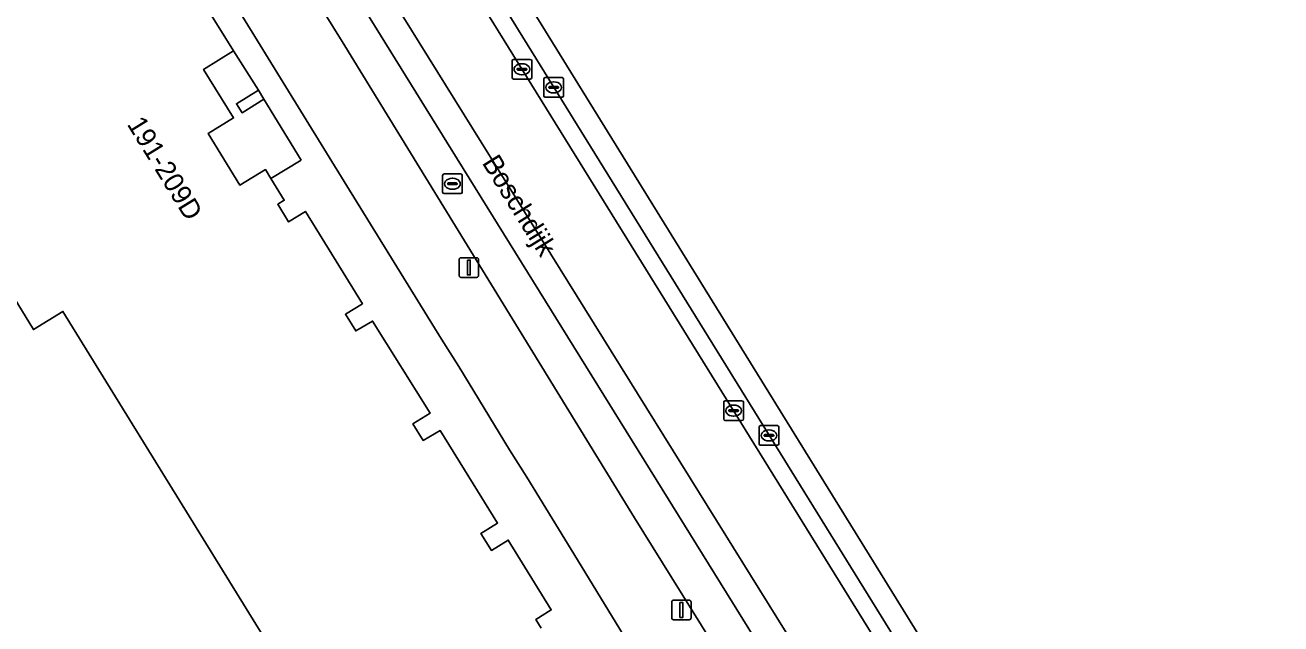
# Model space of a CAD drawing. Extents: x 159888 to 160761, y 384031 to 384750.
# Drawn here: x 160569.1 to 160633, y 384354.7 to 384385.2 of the extents above; entities that cross this region are included whole.
import ezdxf

# ---------------------------------------------------------------- set-up
doc = ezdxf.new("R2010")
doc.units = 0
for name, color, linetype in [('IMGEO_Berm_open', 7, 'Continuous'), ('IMGEO_Erf', 7, 'Continuous'), ('IMGEO_Kolk', 7, 'Continuous'), ('IMGEO_Lichtmast', 7, 'Continuous'), ('IMGEO_Muur', 7, 'Continuous'), ('IMGEO_Openbare_ruimte_label', 7, 'Continuous'), ('IMGEO_Pand', 7, 'Continuous'), ('IMGEO_Pand_nummerreeks', 7, 'Continuous'), ('IMGEO_Pand_overbouw', 7, 'Continuous'), ('IMGEO_Parkeervlak_gesloten', 7, 'Continuous'), ('IMGEO_Rijbaan_lokaal_gesloten', 7, 'Continuous'), ('IMGEO_Rioolput', 7, 'Continuous'), ('IMGEO_Voetpad_open', 7, 'Continuous')]:
    doc.layers.add(name, color=color, linetype=linetype)

msp = doc.modelspace()

# ---------------------------------------------------------------- linework, layer by layer
at = {"layer": 'IMGEO_Berm_open'}
msp.add_lwpolyline([(160573.734, 384418.106), (160547.482, 384460.166), (160546.333, 384462.102), (160545.604, 384461.675), (160546.003, 384460.9), (160546.729, 384459.74), (160564.541, 384431.158), (160615.861, 384348.269), (160631.369, 384323.299), (160632.074, 384323.722), (160631.044, 384325.378)], close=True, dxfattribs=at)
at = {"layer": 'IMGEO_Erf'}
for points in [[(160600.365, 384352.829), (160597.222, 384357.971), (160594.642, 384362.181), (160593.757, 384363.576), (160591.184, 384367.806), (160590.298, 384369.214), (160585.486, 384377.009), (160580.046, 384385.856), (160577.427, 384390.077), (160576.576, 384391.436), (160573.976, 384395.655), (160573.139, 384397.008), (160570.55, 384401.238), (160566.359, 384407.814)], [(160577.492, 384387.466), (160578.932, 384385.154), (160579.715, 384383.896), (160578.196, 384382.943), (160579.718, 384380.474), (160578.421, 384379.675), (160580.035, 384377.056), (160581.338, 384377.848), (160581.621, 384377.388), (160582.302, 384376.281), (160581.969, 384376.076), (160582.52, 384375.182), (160583.379, 384375.711), (160586.275, 384371.011), (160585.411, 384370.479), (160585.935, 384369.628), (160586.793, 384370.131), (160589.717, 384365.431), (160588.848, 384364.899), (160589.37, 384364.046), (160590.239, 384364.551), (160593.157, 384359.834), (160592.309, 384359.309), (160592.846, 384358.444), (160593.698, 384358.972), (160595.887, 384355.417), (160595.104, 384354.934), (160595.373, 384354.493)], [(160582.063, 384352.728), (160571.03, 384370.619), (160569.536, 384369.697), (160567.598, 384372.839)]]:
    msp.add_lwpolyline(points, dxfattribs=at)
msp.add_lwpolyline([(160579.867, 384381.201), (160580.982, 384381.888), (160581.265, 384381.428), (160580.15, 384380.741)], close=True, dxfattribs=at)
at = {"layer": 'IMGEO_Kolk'}
for p, q in [((160593.97, 384383.455), (160594.822, 384383.455)), ((160593.895, 384382.529), (160593.895, 384383.381)), ((160594.154, 384382.949), (160594.154, 384382.961)), ((160594.592, 384382.912), (160594.194, 384382.912)), ((160594.197, 384382.998), (160594.595, 384382.998)), ((160594.383, 384383.235), (160594.408, 384383.235)), ((160594.638, 384382.961), (160594.638, 384382.949)), ((160594.896, 384383.381), (160594.896, 384382.529)), ((160594.822, 384382.455), (160593.97, 384382.455)), ((160594.406, 384382.675), (160594.381, 384382.675)), ((160595.511, 384381.605), (160595.511, 384382.457)), ((160595.586, 384382.531), (160596.438, 384382.531)), ((160595.999, 384382.311), (160596.024, 384382.311)), ((160596.512, 384382.457), (160596.512, 384381.605)), ((160596.438, 384381.531), (160595.586, 384381.531)), ((160595.77, 384382.025), (160595.77, 384382.037)), ((160596.208, 384381.988), (160595.81, 384381.988)), ((160595.813, 384382.074), (160596.211, 384382.074)), ((160596.022, 384381.751), (160595.997, 384381.751)), ((160596.254, 384382.037), (160596.254, 384382.025)), ((160604.668, 384365.141), (160604.668, 384365.993)), ((160604.743, 384366.067), (160605.595, 384366.067)), ((160604.927, 384365.561), (160604.927, 384365.573)), ((160604.97, 384365.61), (160605.368, 384365.61)), ((160605.156, 384365.847), (160605.181, 384365.847)), ((160605.411, 384365.573), (160605.411, 384365.561)), ((160605.669, 384365.993), (160605.669, 384365.141)), ((160605.595, 384365.067), (160604.743, 384365.067)), ((160605.365, 384365.524), (160604.967, 384365.524)), ((160605.179, 384365.287), (160605.154, 384365.287)), ((160606.469, 384363.876), (160606.469, 384364.728)), ((160606.544, 384364.802), (160607.396, 384364.802)), ((160606.728, 384364.296), (160606.728, 384364.308)), ((160607.166, 384364.259), (160606.768, 384364.259)), ((160606.771, 384364.345), (160607.169, 384364.345)), ((160606.957, 384364.582), (160606.982, 384364.582)), ((160607.212, 384364.308), (160607.212, 384364.296)), ((160607.47, 384364.728), (160607.47, 384363.876)), ((160607.396, 384363.802), (160606.544, 384363.802)), ((160606.98, 384364.022), (160606.955, 384364.022))]:
    msp.add_line(p, q, dxfattribs=at)
for points in [[(160593.97, 384383.455), (160594.822, 384383.455)], [(160593.895, 384382.529), (160593.895, 384383.381)], [(160594.896, 384383.381), (160594.896, 384382.529)], [(160594.822, 384382.455), (160593.97, 384382.455)], [(160595.511, 384381.605), (160595.511, 384382.457)], [(160595.586, 384382.531), (160596.438, 384382.531)], [(160596.512, 384382.457), (160596.512, 384381.605)], [(160596.438, 384381.531), (160595.586, 384381.531)], [(160604.668, 384365.141), (160604.668, 384365.993)], [(160604.743, 384366.067), (160605.595, 384366.067)], [(160605.669, 384365.993), (160605.669, 384365.141)], [(160605.595, 384365.067), (160604.743, 384365.067)], [(160606.469, 384363.876), (160606.469, 384364.728)], [(160606.544, 384364.802), (160607.396, 384364.802)], [(160607.47, 384364.728), (160607.47, 384363.876)], [(160607.396, 384363.802), (160606.544, 384363.802)]]:
    msp.add_lwpolyline(points, dxfattribs=at)
for centre, radius, start, end in [((160593.972, 384383.379), 0.0765, 91.55205, 178.44795), ((160593.972, 384383.379), 0.0765, 91.55205, 178.44795), ((160594.82, 384383.379), 0.0765, 1.55205, 88.44795), ((160594.82, 384383.379), 0.0765, 1.55205, 88.44795), ((160594.194, 384382.958), 0.0403, 85.87752, 175.75265), ((160594.191, 384382.948), 0.0366, 178.93798, 274.71019), ((160594.595, 384382.955), 0.043, 264.86636, 352.45326), ((160594.599, 384382.96), 0.0386, 1.73085, 96.63898), ((160593.972, 384382.531), 0.0765, 181.55205, 268.44795), ((160593.972, 384382.531), 0.0765, 181.55205, 268.44795), ((160594.82, 384382.531), 0.0765, 271.55205, 358.44795), ((160594.82, 384382.531), 0.0765, 271.55205, 358.44795), ((160595.588, 384382.455), 0.0765, 91.55205, 178.44795), ((160595.588, 384382.455), 0.0765, 91.55205, 178.44795), ((160596.436, 384382.455), 0.0765, 1.55205, 88.44795), ((160596.436, 384382.455), 0.0765, 1.55205, 88.44795), ((160595.588, 384381.607), 0.0765, 181.55205, 268.44795), ((160595.588, 384381.607), 0.0765, 181.55205, 268.44795), ((160595.81, 384382.034), 0.0403, 85.87752, 175.75265), ((160595.807, 384382.024), 0.0366, 178.93798, 274.71019), ((160596.211, 384382.031), 0.043, 264.86636, 352.45326), ((160596.215, 384382.036), 0.0386, 1.73085, 96.63898), ((160596.436, 384381.607), 0.0765, 271.55205, 358.44795), ((160596.436, 384381.607), 0.0765, 271.55205, 358.44795), ((160604.745, 384365.991), 0.0765, 91.55205, 178.44795), ((160604.745, 384365.991), 0.0765, 91.55205, 178.44795), ((160604.967, 384365.57), 0.0403, 85.87752, 175.75265), ((160604.964, 384365.56), 0.0366, 178.93798, 274.71019), ((160605.368, 384365.567), 0.043, 264.86636, 352.45326), ((160605.372, 384365.572), 0.0386, 1.73085, 96.63898), ((160605.593, 384365.991), 0.0765, 1.55205, 88.44795), ((160605.593, 384365.991), 0.0765, 1.55205, 88.44795), ((160604.745, 384365.143), 0.0765, 181.55205, 268.44795), ((160604.745, 384365.143), 0.0765, 181.55205, 268.44795), ((160605.593, 384365.143), 0.0765, 271.55205, 358.44795), ((160605.593, 384365.143), 0.0765, 271.55205, 358.44795), ((160606.546, 384364.726), 0.0765, 91.55205, 178.44795), ((160606.546, 384364.726), 0.0765, 91.55205, 178.44795), ((160606.768, 384364.305), 0.0403, 85.87752, 175.75265), ((160606.765, 384364.295), 0.0366, 178.93798, 274.71019), ((160607.169, 384364.302), 0.043, 264.86636, 352.45326), ((160607.173, 384364.307), 0.0386, 1.73085, 96.63898), ((160607.394, 384364.726), 0.0765, 1.55205, 88.44795), ((160607.394, 384364.726), 0.0765, 1.55205, 88.44795), ((160606.546, 384363.878), 0.0765, 181.55205, 268.44795), ((160606.546, 384363.878), 0.0765, 181.55205, 268.44795), ((160607.394, 384363.878), 0.0765, 271.55205, 358.44795), ((160607.394, 384363.878), 0.0765, 271.55205, 358.44795)]:
    msp.add_arc(centre, radius, start, end, dxfattribs=at)
for centre, major_axis, ratio, start_param, end_param in [((160594.382, 384382.955), (-0.387, 0.002), 0.722429, 4.712389, 7.853982), ((160594.407, 384382.955), (-0.39, 0.002), 0.717154, 1.570796, 4.712389), ((160595.998, 384382.031), (-0.387, 0.002), 0.722429, 4.712389, 7.853982), ((160596.023, 384382.031), (-0.39, 0.002), 0.717154, 1.570796, 4.712389), ((160605.155, 384365.567), (-0.387, 0.002), 0.722429, 4.712389, 7.853982), ((160605.18, 384365.567), (-0.39, 0.002), 0.717154, 1.570796, 4.712389), ((160606.956, 384364.302), (-0.387, 0.002), 0.722429, 4.712389, 7.853982), ((160606.981, 384364.302), (-0.39, 0.002), 0.717154, 1.570796, 4.712389)]:
    msp.add_ellipse(centre, major_axis=major_axis, ratio=ratio, start_param=start_param, end_param=end_param, dxfattribs=at)
at = {"layer": 'IMGEO_Lichtmast'}
for p, q in [((160591.198, 384372.456), (160591.198, 384373.256)), ((160591.198, 384373.256), (160591.198, 384372.456)), ((160591.298, 384373.356), (160592.088, 384373.356)), ((160592.088, 384373.356), (160591.298, 384373.356)), ((160592.188, 384373.256), (160592.188, 384372.456)), ((160592.188, 384372.456), (160592.188, 384373.256)), ((160592.088, 384372.356), (160591.298, 384372.356)), ((160591.298, 384372.356), (160592.088, 384372.356)), ((160602.017, 384355.011), (160602.017, 384355.811)), ((160602.017, 384355.811), (160602.017, 384355.011)), ((160602.117, 384355.911), (160602.907, 384355.911)), ((160602.907, 384355.911), (160602.117, 384355.911)), ((160603.007, 384355.811), (160603.007, 384355.011)), ((160603.007, 384355.011), (160603.007, 384355.811)), ((160602.907, 384354.911), (160602.117, 384354.911)), ((160602.117, 384354.911), (160602.907, 384354.911))]:
    msp.add_line(p, q, dxfattribs=at)
for points in [[(160591.618, 384373.231), (160591.768, 384373.231), (160591.768, 384372.481), (160591.618, 384372.481), (160591.618, 384373.231)], [(160602.437, 384355.786), (160602.587, 384355.786), (160602.587, 384355.036), (160602.437, 384355.036), (160602.437, 384355.786)]]:
    msp.add_lwpolyline(points, dxfattribs=at)
for centre, start, end in [((160591.298, 384373.256), 90, 180), ((160591.298, 384373.256), 90, 180), ((160592.088, 384373.256), 0, 90), ((160592.088, 384373.256), 360, 90), ((160591.298, 384372.456), 180, 270), ((160591.298, 384372.456), 180, 270), ((160592.088, 384372.456), 270, 0), ((160592.088, 384372.456), 270, 0), ((160602.117, 384355.811), 90, 180), ((160602.117, 384355.811), 90, 180), ((160602.907, 384355.811), 0, 90), ((160602.907, 384355.811), 360, 90), ((160602.117, 384355.011), 180, 270), ((160602.117, 384355.011), 180, 270), ((160602.907, 384355.011), 270, 0), ((160602.907, 384355.011), 270, 0)]:
    msp.add_arc(centre, 0.1, start, end, dxfattribs=at)
at = {"layer": 'IMGEO_Muur'}
for points in [[(160585.486, 384377.009), (160590.298, 384369.214)], [(160591.184, 384367.806), (160593.757, 384363.576)], [(160594.642, 384362.181), (160597.222, 384357.971)]]:
    msp.add_lwpolyline(points, dxfattribs=at)
at = {"layer": 'IMGEO_Pand'}
for points in [[(160595.373, 384354.493), (160595.104, 384354.934), (160595.887, 384355.417), (160593.698, 384358.972), (160592.846, 384358.444), (160592.309, 384359.309), (160593.157, 384359.834), (160590.239, 384364.551), (160589.37, 384364.046), (160588.848, 384364.899), (160589.717, 384365.431), (160586.793, 384370.131), (160585.935, 384369.628), (160585.411, 384370.479), (160586.275, 384371.011), (160583.379, 384375.711), (160582.52, 384375.182), (160581.969, 384376.076), (160582.302, 384376.281), (160581.621, 384377.388), (160581.338, 384377.848), (160580.035, 384377.056), (160578.421, 384379.675), (160579.718, 384380.474), (160578.196, 384382.943), (160579.715, 384383.896), (160578.932, 384385.154), (160577.492, 384387.466)], [(160567.598, 384372.839), (160569.536, 384369.697), (160571.03, 384370.619), (160582.063, 384352.728)]]:
    msp.add_lwpolyline(points, dxfattribs=at)
msp.add_lwpolyline([(160581.265, 384381.428), (160580.982, 384381.888), (160579.867, 384381.201), (160580.15, 384380.741)], close=True, dxfattribs=at)
at = {"layer": 'IMGEO_Pand_overbouw'}
msp.add_lwpolyline([(160583.168, 384378.329), (160581.265, 384381.428), (160580.15, 384380.741), (160579.867, 384381.201), (160580.982, 384381.888), (160579.715, 384383.896), (160578.196, 384382.943), (160579.718, 384380.474), (160578.421, 384379.675), (160580.035, 384377.056), (160581.338, 384377.848), (160581.621, 384377.388)], close=True, dxfattribs=at)
at = {"layer": 'IMGEO_Parkeervlak_gesloten'}
for points in [[(160591.404, 384377.897), (160543.713, 384454.868), (160537.603, 384464.743), (160537.564, 384464.718)], [(160537.553, 384461.036), (160540.083, 384456.992), (160542.538, 384453.014), (160544.582, 384449.757), (160546.017, 384447.47), (160547.886, 384444.522), (160552.792, 384436.596), (160555.44, 384432.318), (160560.546, 384424.068), (160561.084, 384423.337), (160563.566, 384419.321), (160564.854, 384417.108), (160570.857, 384407.526), (160585.252, 384384.362), (160600.12, 384360.1), (160613.675, 384338.3), (160614.145, 384337.587), (160615.758, 384338.612), (160591.404, 384377.897)]]:
    msp.add_lwpolyline(points, dxfattribs=at)
at = {"layer": 'IMGEO_Rijbaan_lokaal_gesloten'}
for points in [[(160530.872, 384485.299), (160529.392, 384487.663), (160528.599, 384488.928), (160527.089, 384491.477), (160521.986, 384499.927), (160522.875, 384494.017), (160521.397, 384493.999), (160525.927, 384486.643), (160525.936, 384486.628), (160565.675, 384422.118), (160628.254, 384321.427), (160631.369, 384323.299), (160615.861, 384348.269), (160564.541, 384431.158), (160546.729, 384459.74), (160546.003, 384460.9), (160545.604, 384461.675)], [(160633.021, 384324.291), (160626.323, 384335.141), (160581.707, 384407.406), (160547.381, 384462.76), (160546.333, 384462.102), (160547.482, 384460.166), (160573.734, 384418.106), (160631.044, 384325.378), (160632.074, 384323.722), (160633.021, 384324.291)]]:
    msp.add_lwpolyline(points, dxfattribs=at)
msp.add_lwpolyline([(160525.936, 384486.628), (160525.927, 384486.643), (160521.397, 384493.999), (160519.494, 384493.976), (160523.701, 384487.143), (160524.133, 384486.422), (160537.603, 384464.743), (160543.713, 384454.868), (160591.404, 384377.897), (160615.758, 384338.612), (160624.721, 384324.154), (160626.898, 384320.642), (160628.254, 384321.427), (160565.675, 384422.118)], close=True, dxfattribs=at)
at = {"layer": 'IMGEO_Rioolput'}
for p, q in [((160590.358, 384376.694), (160590.358, 384377.546)), ((160590.433, 384377.62), (160591.285, 384377.62)), ((160590.617, 384377.114), (160590.617, 384377.126)), ((160591.055, 384377.077), (160590.657, 384377.077)), ((160590.66, 384377.163), (160591.058, 384377.163)), ((160590.846, 384377.4), (160590.871, 384377.4)), ((160591.101, 384377.126), (160591.101, 384377.114)), ((160591.359, 384377.546), (160591.359, 384376.694)), ((160591.285, 384376.62), (160590.433, 384376.62)), ((160590.869, 384376.84), (160590.844, 384376.84))]:
    msp.add_line(p, q, dxfattribs=at)
for points in [[(160590.358, 384376.694), (160590.358, 384377.546)], [(160590.433, 384377.62), (160591.285, 384377.62)], [(160591.359, 384377.546), (160591.359, 384376.694)], [(160591.285, 384376.62), (160590.433, 384376.62)]]:
    msp.add_lwpolyline(points, dxfattribs=at)
for centre, radius, start, end in [((160590.435, 384377.544), 0.0765, 91.55205, 178.44795), ((160590.435, 384377.544), 0.0765, 91.55205, 178.44795), ((160590.657, 384377.123), 0.0403, 85.87752, 175.75265), ((160590.654, 384377.113), 0.0366, 178.93798, 274.71019), ((160591.058, 384377.12), 0.043, 264.86636, 352.45326), ((160591.062, 384377.125), 0.0386, 1.73085, 96.63898), ((160591.283, 384377.544), 0.0765, 1.55205, 88.44795), ((160591.283, 384377.544), 0.0765, 1.55205, 88.44795), ((160590.435, 384376.696), 0.0765, 181.55205, 268.44795), ((160590.435, 384376.696), 0.0765, 181.55205, 268.44795), ((160591.283, 384376.696), 0.0765, 271.55205, 358.44795), ((160591.283, 384376.696), 0.0765, 271.55205, 358.44795)]:
    msp.add_arc(centre, radius, start, end, dxfattribs=at)
for centre, major_axis, ratio, start_param, end_param in [((160590.845, 384377.12), (-0.387, 0.002), 0.722429, 4.712389, 7.853982), ((160590.87, 384377.12), (-0.39, 0.002), 0.717154, 1.570796, 4.712389)]:
    msp.add_ellipse(centre, major_axis=major_axis, ratio=ratio, start_param=start_param, end_param=end_param, dxfattribs=at)
at = {"layer": 'IMGEO_Voetpad_open'}
for points in [[(160585.252, 384384.362), (160570.857, 384407.526), (160564.854, 384417.108)], [(160566.359, 384407.814), (160570.55, 384401.238), (160573.139, 384397.008), (160573.976, 384395.655), (160576.576, 384391.436), (160577.427, 384390.077), (160580.046, 384385.856), (160585.486, 384377.009), (160590.298, 384369.214), (160591.184, 384367.806), (160593.757, 384363.576), (160594.642, 384362.181), (160597.222, 384357.971), (160600.365, 384352.829), (160601.085, 384351.65), (160603.742, 384347.414), (160603.953, 384347.074), (160606.584, 384342.823), (160606.794, 384342.482), (160609.425, 384338.231), (160611.084, 384335.6), (160612.124, 384331.359)], [(160614.431, 384337.013), (160614.289, 384337.297), (160614.145, 384337.587), (160613.675, 384338.3), (160600.12, 384360.1), (160585.252, 384384.362)]]:
    msp.add_lwpolyline(points, dxfattribs=at)

# ---------------------------------------------------------------- texts
at = {"layer": 'IMGEO_Openbare_ruimte_label'}
msp.add_text('Boschdijk', height=1, rotation=301.87782, dxfattribs=at).set_placement((160592.336, 384378.192))
at = {"layer": 'IMGEO_Pand_nummerreeks'}
msp.add_text('191-209D', height=1, rotation=301.64425, dxfattribs=at).set_placement((160574.27, 384380.159))

doc.saveas('drawing.dxf')
